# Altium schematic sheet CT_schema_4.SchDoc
size 296 x 173 mm
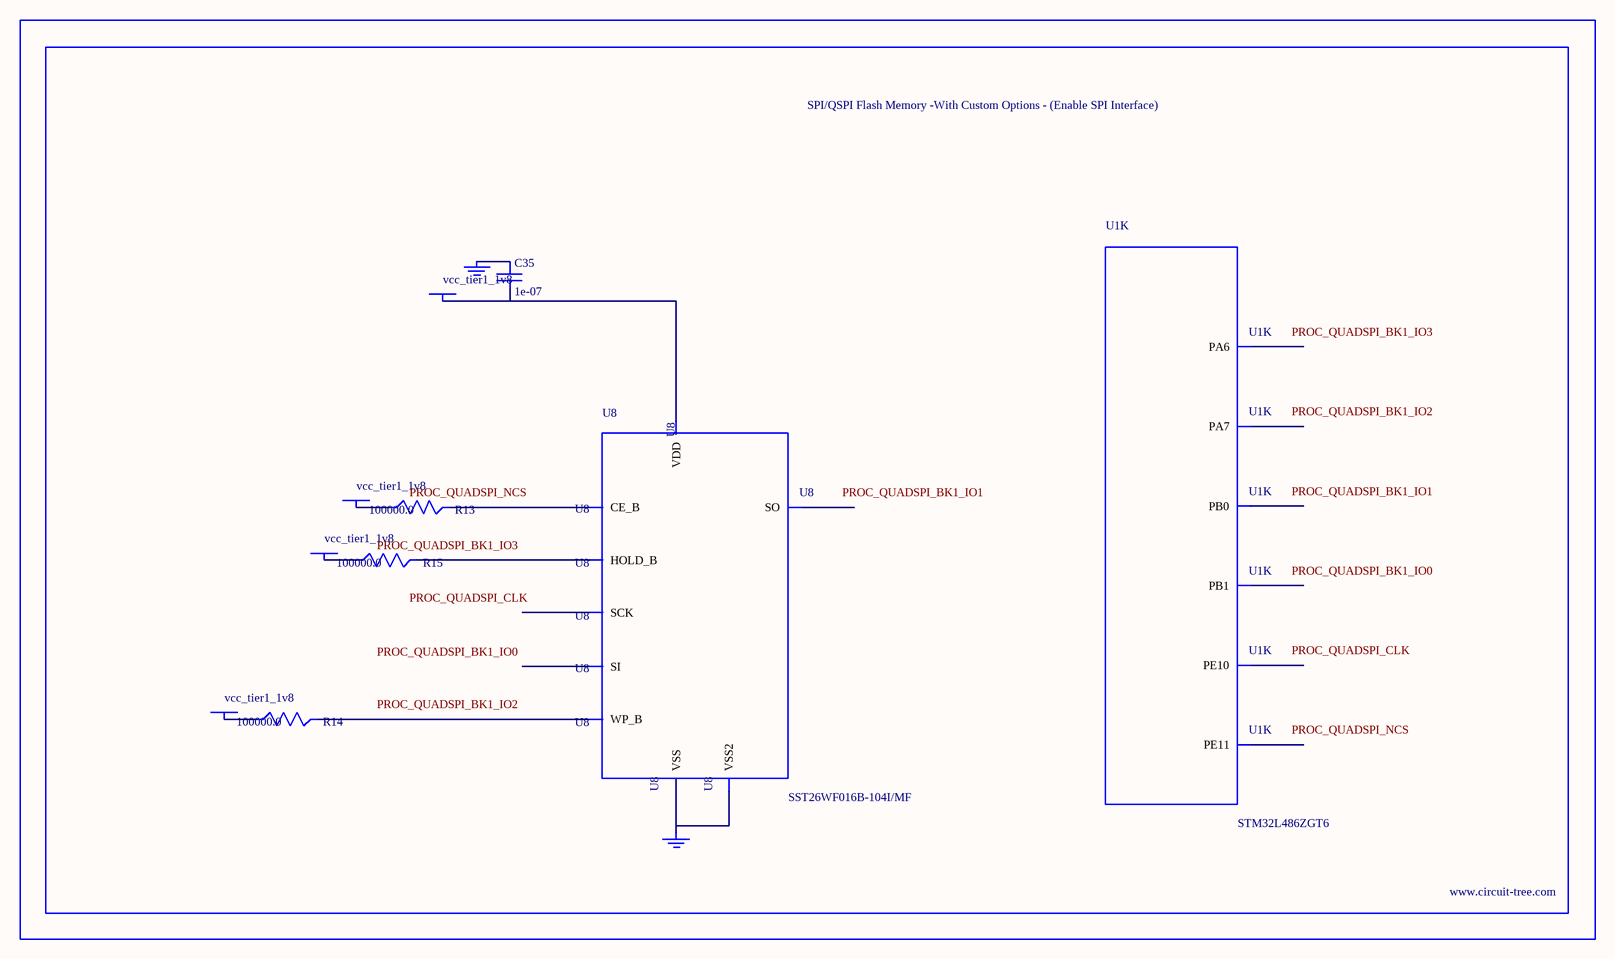
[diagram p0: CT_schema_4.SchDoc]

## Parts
BORDER3  (no value)
C35  1e-07  [C0402]
GND_INSTANCE_3_0  (no value)
GND_INSTANCE_3_1  (no value)
POWER_INSTANCE_3_0  vcc_tier1_1v8
POWER_INSTANCE_3_1  vcc_tier1_1v8
POWER_INSTANCE_3_2  vcc_tier1_1v8
POWER_INSTANCE_3_3  vcc_tier1_1v8
R13  100000.0  [R0603]
R14  100000.0  [R0603]
R15  100000.0  [R0603]
U1  STM32L486ZGT6  [LQFP144]  (part K of 11)
U8  SST26WF016B-104I/MF  [WFDN-8]

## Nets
NetC35_1: C35.1 GND_INSTANCE_3_0.0(GND)
NetC35_2: C35.2 POWER_INSTANCE_3_3.0(PWR) U8.8(VDD)
NetGND_INSTANCE_3_1_0: GND_INSTANCE_3_1.0(GND) U8.4(VSS) U8.9(VSS2)
NetPOWER_INSTANCE_3_0_0: POWER_INSTANCE_3_0.0(PWR) R13.1
NetPOWER_INSTANCE_3_1_0: POWER_INSTANCE_3_1.0(PWR) R14.1
NetPOWER_INSTANCE_3_2_0: POWER_INSTANCE_3_2.0(PWR) R15.1
NetR13_2: R13.2 U8.1(CE_B)
NetR14_2: R14.2 U8.3(WP_B)
NetR15_2: R15.2 U8.7(HOLD_B)

Not connected (* = marked no-connect by the designer): U1 42(PA6) 43(PA7) 46(PB0) 47(PB1) 63(PE10) 64(PE11); U8 2(SO) 5(SI) 6(SCK)

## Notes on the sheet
- Labels drawn without touching a wire or pin: PROC_QUADSPI_BK1_IO0, PROC_QUADSPI_BK1_IO1, PROC_QUADSPI_BK1_IO2, PROC_QUADSPI_BK1_IO3, PROC_QUADSPI_CLK, PROC_QUADSPI_NCS

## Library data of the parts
BORDER3 = BORDER_PAGE3
C35 = C0402C104K3RACTU
GND_INSTANCE_3_0 GND_INSTANCE_3_1 = GND
POWER_INSTANCE_3_0-POWER_INSTANCE_3_3 = PWR
R13-R15 = RC0603JR-07100KL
